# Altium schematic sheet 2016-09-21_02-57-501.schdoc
size 344 x 125 mm; SheetNumber: 1; SheetTotal: 1
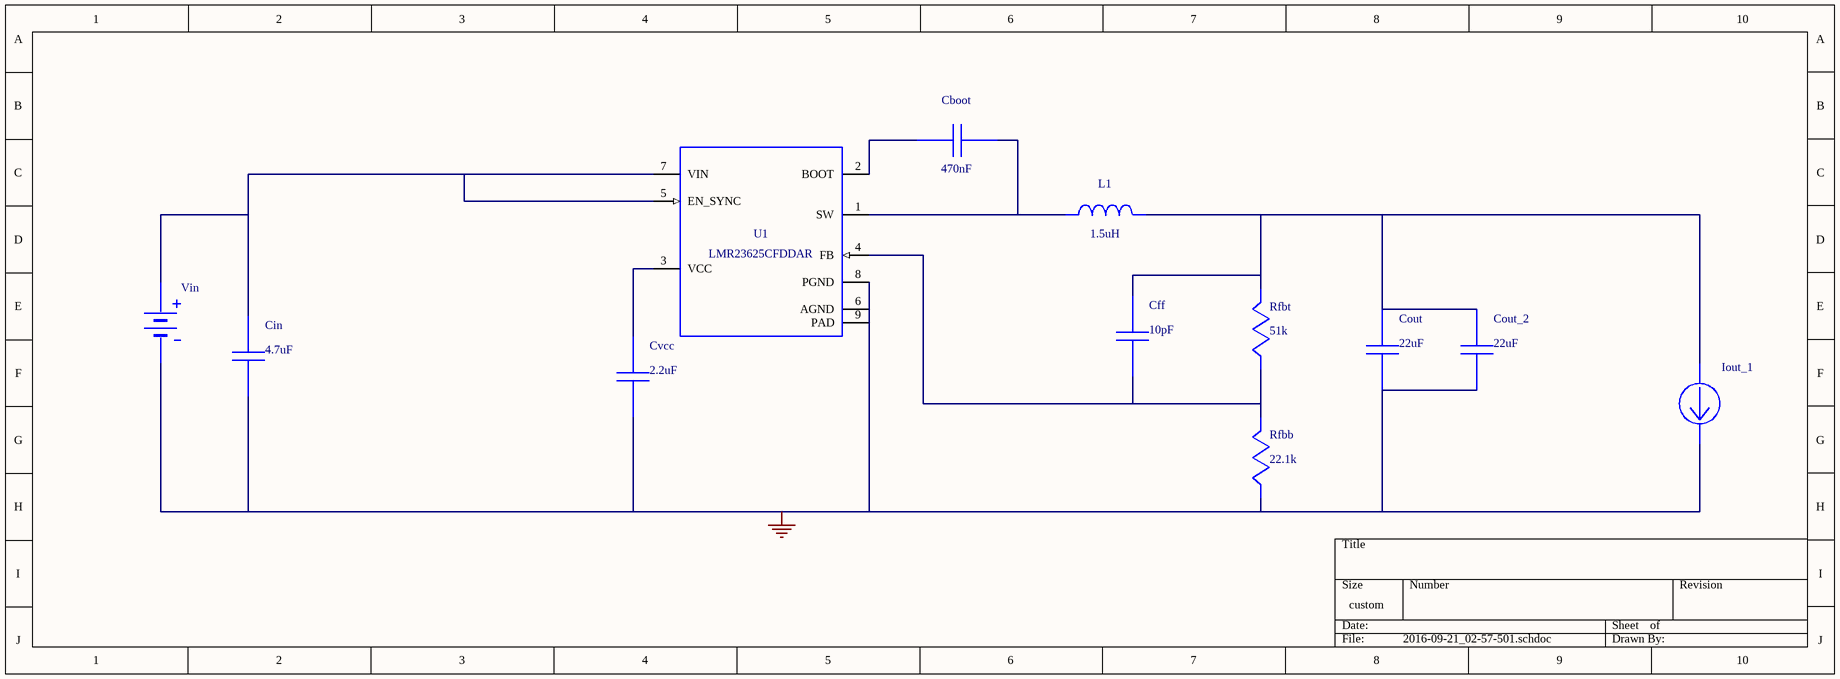
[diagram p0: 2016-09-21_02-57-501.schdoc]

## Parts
Cboot  value 470nF  (hidden comment: GMK212BJ474KG-T)
Cff  value 10pF  (hidden comment: C0805C100M4GACTU)
Cin  value 4.7uF  (hidden comment: GRM32ER71H475KA88L)
Cout  value 22uF  (hidden comment: GRM21BR60J226ME39L)
Cout_2  value 22uF  (hidden comment: GRM21BR60J226ME39L)
Cvcc  value 2.2uF  (hidden comment: GRM188R60J225KE19D)
Iout_1  WB_CURRENT_LOAD  (value not drawn)
L1  value 1.5uH  (hidden comment: IHLP1212BZER1R5M11)
Rfbb  value 22.1k  (hidden comment: ERJ-6ENF2212V)
Rfbt  value 51k  (hidden comment: RC0603FR-0751KL)
U1  LMR23625CFDDAR
Vin  WB_BATTERY  (value not drawn)

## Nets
0: Cin.2 Cout.2 Cout_2.2 Cvcc.2 Iout_1.2(-) Rfbb.2 U1.6(AGND) U1.8(PGND) U1.9(PAD) Vin.2(-)
NetCboot_1: Cboot.1 U1.2(BOOT)
NetCboot_2: Cboot.2 L1.1 U1.1(SW)
NetCff_1: Cff.1 Cout.1 Cout_2.1 Iout_1.1(+) L1.2 Rfbt.1
NetCff_2: Cff.2 Rfbb.1 Rfbt.2 U1.4(FB)
NetCin_1: Cin.1 U1.5(EN_SYNC) U1.7(VIN) Vin.1(+)
NetCvcc_1: Cvcc.1 U1.3(VCC)

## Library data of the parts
Cboot = GMK212BJ474KG-T: Manufacturer Name: Taiyo Yuden
Cff = C0805C100M4GACTU: Manufacturer Name: Kemet
Cin = GRM32ER71H475KA88L: GRM32ER71H475KA8; Manufacturer Name: MuRata
Cout Cout_2 = GRM21BR60J226ME39L: GRM21BR60J226ME3; Manufacturer Name: MuRata
Cvcc = GRM188R60J225KE19D: GRM188R60J225KE1; Manufacturer Name: MuRata
L1 = IHLP1212BZER1R5M11: Unknown; Manufacturer Name: Vishay-Dale
Rfbb = ERJ-6ENF2212V: Manufacturer Name: Panasonic
Rfbt = RC0603FR-0751KL: Manufacturer Name: Yageo America
U1 = LMR23625CFDDAR: Manufacturer Name: Texas Instruments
